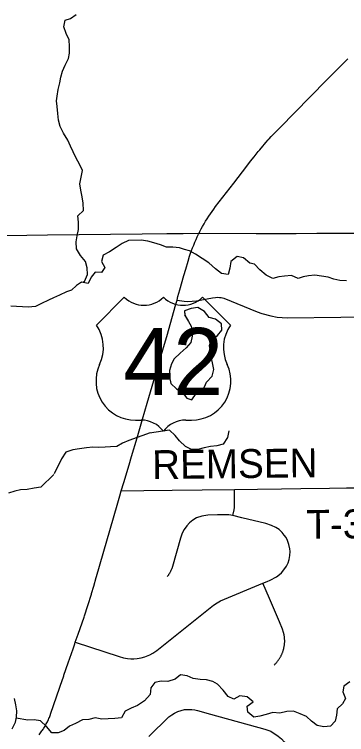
# Model space of a CAD drawing. Extents: x 0 to 34, y 0 to 22.
# Drawn here: x 4.89 to 5.217, y 17.083 to 17.791 of the extents above; entities that cross this region are included whole.
import ezdxf

# ---------------------------------------------------------------- set-up
doc = ezdxf.new("R2010")
doc.units = 0
for name, color, linetype in [('GM_X_County_Road', 7, 'Continuous'), ('GM_X_Major_River', 7, 'Continuous'), ('GM_X_Minor_Lake', 7, 'Continuous'), ('GM_X_Minor_River', 7, 'Continuous'), ('GM_X_Township_Road', 7, 'Continuous'), ('GM_X_Township_Road_Text', 7, 'Continuous'), ('GM_X_US_Location', 7, 'Continuous'), ('GM_X_US_Route', 7, 'Continuous'), ('GM_X_US_Shield', 7, 'Continuous')]:
    doc.layers.add(name, color=color, linetype=linetype)

msp = doc.modelspace()

# ---------------------------------------------------------------- linework, layer by layer
at = {"layer": 'GM_X_County_Road'}
msp.add_lwpolyline([(4.86958, 17.57352), (4.90274, 17.57389), (4.92294, 17.57412), (5.01604, 17.57515), (5.04025, 17.57542), (5.04952, 17.5755), (5.05644, 17.57557), (5.07194, 17.5758), (5.12823, 17.57567), (5.16738, 17.57558), (5.18772, 17.57575), (5.20217, 17.57592), (5.20847, 17.576), (5.22729, 17.57592)], dxfattribs=at)
at = {"layer": 'GM_X_Major_River'}
msp.add_lwpolyline([(4.88817, 17.08829), (4.89138, 17.09493), (4.89251, 17.09987), (4.89269, 17.10594), (4.89174, 17.11201), (4.89041, 17.11827)], dxfattribs=at)
at = {"layer": 'GM_X_Minor_Lake'}
for points in [[(5.07839, 17.42697), (5.07915, 17.42925), (5.08482, 17.43513), (5.08652, 17.44177), (5.08557, 17.44652), (5.08406, 17.45296), (5.0833, 17.45922), (5.08216, 17.46529), (5.08405, 17.47098), (5.0901, 17.47516), (5.09426, 17.48028), (5.09388, 17.48654), (5.0882, 17.49109), (5.08196, 17.49299), (5.07742, 17.49886), (5.07079, 17.50284), (5.06417, 17.50189), (5.05774, 17.49942), (5.05791, 17.49516)], [(5.07839, 17.42697), (5.07915, 17.42925), (5.08482, 17.43513), (5.08652, 17.44177), (5.08557, 17.44652), (5.08406, 17.45296), (5.0833, 17.45922), (5.08216, 17.46529), (5.08405, 17.47098), (5.0901, 17.47516), (5.09426, 17.48028), (5.09388, 17.48654), (5.0882, 17.49109), (5.08196, 17.49299), (5.07742, 17.49886), (5.07079, 17.50284), (5.06417, 17.50189), (5.05774, 17.49942), (5.05793, 17.49468)], [(5.05774, 17.49544), (5.06172, 17.48899), (5.06418, 17.48425), (5.06532, 17.47951), (5.06513, 17.47439), (5.064, 17.46832), (5.05927, 17.463), (5.05341, 17.45769), (5.04736, 17.45219), (5.04472, 17.44744), (5.04302, 17.4408), (5.04283, 17.43435), (5.04416, 17.42791), (5.04983, 17.4226), (5.05551, 17.41938), (5.05986, 17.41369), (5.06478, 17.41179), (5.06913, 17.41805), (5.07537, 17.42071), (5.07839, 17.42697)], [(5.05791, 17.49516), (5.06172, 17.48899), (5.06418, 17.48425), (5.06532, 17.47951), (5.06513, 17.47439), (5.064, 17.46832), (5.05927, 17.463), (5.05341, 17.45769), (5.04736, 17.45219), (5.04472, 17.44744), (5.04302, 17.4408), (5.04283, 17.43435), (5.04416, 17.42791), (5.04983, 17.4226), (5.05551, 17.41938), (5.05986, 17.41369), (5.06478, 17.41179), (5.06913, 17.41805), (5.07537, 17.42071), (5.07839, 17.42697)]]:
    msp.add_lwpolyline(points, dxfattribs=at)
at = {"layer": 'GM_X_Minor_River'}
for points in [[(4.95649, 17.52763), (4.9595, 17.52846), (4.96218, 17.53535), (4.96203, 17.5418), (4.96019, 17.54783), (4.95532, 17.55378), (4.95139, 17.56033), (4.95104, 17.56734), (4.95204, 17.57325), (4.9534, 17.57954), (4.95343, 17.58656), (4.95272, 17.5928), (4.95846, 17.59825), (4.95792, 17.60526), (4.95702, 17.6115), (4.95573, 17.6181), (4.95464, 17.62453), (4.95619, 17.63083), (4.95736, 17.63749), (4.95438, 17.64387), (4.95122, 17.64949), (4.94824, 17.65587), (4.94546, 17.6615), (4.94287, 17.66732), (4.93874, 17.67425), (4.93557, 17.68062), (4.93391, 17.68684), (4.933, 17.69346), (4.93265, 17.70028), (4.93196, 17.70596), (4.93242, 17.71071), (4.9334, 17.71719), (4.93495, 17.72386), (4.93596, 17.7292), (4.93771, 17.73531), (4.94041, 17.74125), (4.94366, 17.74778), (4.94449, 17.75292), (4.94472, 17.75938), (4.94419, 17.766), (4.94139, 17.77239), (4.93898, 17.77878), (4.94034, 17.78546), (4.9456, 17.78691), (4.95118, 17.79102)], [(5.17968, 17.53394), (5.17422, 17.53286), (5.16934, 17.53123), (5.16285, 17.53412), (5.15605, 17.53339), (5.15039, 17.53288), (5.14438, 17.53141), (5.13787, 17.53468), (5.1317, 17.53985), (5.12647, 17.54541), (5.12172, 17.54625), (5.11574, 17.55143), (5.10946, 17.55299), (5.10334, 17.54792), (5.10235, 17.54144), (5.10061, 17.53514), (5.09415, 17.53632), (5.08799, 17.54092), (5.08143, 17.54665), (5.0749, 17.55086), (5.06856, 17.55527), (5.06263, 17.55835), (5.05768, 17.55976), (5.05273, 17.56135), (5.04609, 17.56215), (5.04004, 17.56201), (5.03394, 17.56433), (5.02746, 17.56627), (5.02175, 17.56784), (5.01492, 17.56882), (5.00264, 17.56854), (4.99646, 17.56574), (4.9905, 17.56162), (4.98379, 17.55748), (4.97763, 17.55411), (4.97607, 17.548), (4.97923, 17.5422), (4.97594, 17.537), (4.96988, 17.53762), (4.96583, 17.53259), (4.96295, 17.52627), (4.95649, 17.52763), (4.95165, 17.52448), (4.94646, 17.51981), (4.94159, 17.51799), (4.93485, 17.51499), (4.92886, 17.51239), (4.92381, 17.50999), (4.91707, 17.5068), (4.91109, 17.50363), (4.90411, 17.50309), (4.89843, 17.50334), (4.89237, 17.50357), (4.88688, 17.50402)], [(5.21705, 17.52892), (5.21043, 17.52915), (5.20453, 17.53053), (5.19881, 17.53248), (5.19217, 17.53347), (5.18572, 17.53446), (5.17968, 17.53394)], [(5.02376, 17.37933), (5.00301, 17.37202), (4.99664, 17.36921), (4.99105, 17.36605), (4.985, 17.36572), (4.97953, 17.36521), (4.97291, 17.36506), (4.96761, 17.36532), (4.9612, 17.3646), (4.95441, 17.36368), (4.94782, 17.36258), (4.94106, 17.36053), (4.93668, 17.35379), (4.9294, 17.33905)], [(5.10113, 17.3813), (5.09977, 17.37482), (5.09557, 17.36828), (5.08955, 17.36662), (5.08333, 17.36591), (5.07693, 17.36462), (5.07073, 17.36315), (5.06448, 17.36319), (5.05875, 17.36591), (5.05276, 17.37146), (5.04848, 17.37667), (5.04286, 17.38223), (5.02331, 17.37922)], [(4.92917, 17.33848), (4.91652, 17.326), (4.90992, 17.32509), (4.90314, 17.3238), (4.89653, 17.32326), (4.89089, 17.322), (4.8845, 17.32014)], [(5.1318, 17.10067), (5.12596, 17.09978), (5.11999, 17.10457), (5.11928, 17.11063), (5.12505, 17.11494), (5.11926, 17.11993), (5.11205, 17.12071), (5.10608, 17.11734), (5.10053, 17.12025), (5.09566, 17.1264), (5.09023, 17.13215), (5.08545, 17.1347), (5.07935, 17.13665), (5.07292, 17.13688), (5.06628, 17.13767), (5.06017, 17.14038), (5.05371, 17.14155), (5.04832, 17.13726), (5.04138, 17.13501), (5.03457, 17.13523), (5.02836, 17.13376), (5.02451, 17.12855), (5.0239, 17.12208), (5.01837, 17.11589), (5.01148, 17.11136), (5.0053, 17.10875), (4.99932, 17.10558), (4.99569, 17.09924), (4.98927, 17.09852), (4.98248, 17.09798), (4.97643, 17.09784), (4.96978, 17.09921), (4.96358, 17.09754), (4.95754, 17.09703), (4.95062, 17.09345), (4.94463, 17.09104), (4.93924, 17.08674), (4.93343, 17.08452), (4.92738, 17.08438), (4.92194, 17.0907), (4.91615, 17.09607), (4.90988, 17.09725), (4.90365, 17.09673), (4.89221, 17.09883)], [(5.22009, 17.1344), (5.21414, 17.13028), (5.21332, 17.12457), (5.21593, 17.11799), (5.21302, 17.11299), (5.20765, 17.10812), (5.20705, 17.10165), (5.20585, 17.09594), (5.20105, 17.09089), (5.19445, 17.09017), (5.18818, 17.09154), (5.1826, 17.09578), (5.17757, 17.10059), (5.17146, 17.10292), (5.16478, 17.10561), (5.15817, 17.10527), (5.15121, 17.10359), (5.14458, 17.10438), (5.138, 17.10252), (5.1318, 17.10067)]]:
    msp.add_lwpolyline(points, dxfattribs=at)
at = {"layer": 'GM_X_Township_Road'}
for points in [[(5.05041, 17.51006), (5.05727, 17.50895), (5.06029, 17.50864), (5.0653, 17.50882), (5.06936, 17.50944), (5.0853, 17.51236), (5.08813, 17.5127), (5.08982, 17.51285), (5.09195, 17.51272), (5.09358, 17.51248), (5.09638, 17.51184), (5.12913, 17.49854), (5.13367, 17.49673), (5.14237, 17.49444), (5.14865, 17.49329), (5.15872, 17.49252), (5.21139, 17.49312), (5.24624, 17.49378)], [(4.99555, 17.3225), (5.01777, 17.3227), (5.04547, 17.32305), (5.07495, 17.32329), (5.10669, 17.32359), (5.12947, 17.32399), (5.15286, 17.32423), (5.17216, 17.32456), (5.20008, 17.32503), (5.21676, 17.32534), (5.26254, 17.32544)], [(5.10509, 17.29829), (5.10611, 17.30235), (5.10622, 17.30283), (5.10632, 17.30332), (5.10641, 17.3038), (5.1065, 17.30429), (5.10658, 17.30478), (5.10665, 17.30527), (5.10671, 17.30576), (5.10675, 17.30626), (5.1068, 17.30675), (5.10683, 17.30725), (5.10669, 17.32359)], [(4.95031, 17.17343), (4.99347, 17.15943), (4.99778, 17.15822), (5.00159, 17.15746), (5.00491, 17.15715), (5.00799, 17.15721), (5.01125, 17.15742), (5.01513, 17.15813), (5.01873, 17.15921), (5.02344, 17.16108), (5.02667, 17.16278), (5.03051, 17.16551), (5.06142, 17.19029), (5.08628, 17.21), (5.08965, 17.2123), (5.09297, 17.2141), (5.13476, 17.23159), (5.13886, 17.23327), (5.142, 17.23466), (5.14812, 17.23765), (5.15104, 17.23999), (5.15301, 17.2419), (5.15534, 17.24461), (5.15789, 17.24834), (5.15953, 17.2517), (5.16051, 17.25495), (5.16121, 17.25864), (5.16142, 17.26258), (5.16113, 17.26541), (5.16031, 17.26972), (5.159, 17.27353), (5.15756, 17.27636), (5.15575, 17.2789), (5.15366, 17.28149), (5.15067, 17.28424), (5.14751, 17.28637), (5.14328, 17.28838), (5.13771, 17.29018), (5.11396, 17.29589), (5.10509, 17.29829), (5.10115, 17.29874), (5.08995, 17.29866), (5.08051, 17.29842), (5.07473, 17.29764), (5.06948, 17.29579), (5.06578, 17.29366), (5.06254, 17.29087), (5.05984, 17.288), (5.05733, 17.28435), (5.05549, 17.28082), (5.05372, 17.27573), (5.04585, 17.24804), (5.04556, 17.2471), (5.0454, 17.24663), (5.04523, 17.24616), (5.04505, 17.2457), (5.04487, 17.24524), (5.04468, 17.24478), (5.04448, 17.24433), (5.04427, 17.24388), (5.04405, 17.24343), (5.04383, 17.24298), (5.0436, 17.24255), (5.04336, 17.24211), (5.04311, 17.24168), (5.04286, 17.24125), (5.0426, 17.24083), (5.04233, 17.24041), (5.04205, 17.24), (5.04177, 17.23959), (5.04148, 17.23919), (5.04119, 17.23879), (5.04057, 17.23801)], [(5.14565, 17.15089), (5.14648, 17.15169), (5.14689, 17.15211), (5.14728, 17.15252), (5.14767, 17.15295), (5.14806, 17.15339), (5.14843, 17.15382), (5.1488, 17.15427), (5.14916, 17.15472), (5.14951, 17.15518), (5.14985, 17.15565), (5.15019, 17.15612), (5.15051, 17.15659), (5.15083, 17.15708), (5.15115, 17.15757), (5.15145, 17.15806), (5.15174, 17.15856), (5.15202, 17.15906), (5.1523, 17.15957), (5.15257, 17.16008), (5.15282, 17.1606), (5.15307, 17.16112), (5.15331, 17.16165), (5.15354, 17.16218), (5.15376, 17.16272), (5.15398, 17.16326), (5.15418, 17.1638), (5.15437, 17.16434), (5.15455, 17.16489), (5.15473, 17.16545), (5.15489, 17.166), (5.15504, 17.16656), (5.15519, 17.16712), (5.15532, 17.16768), (5.15545, 17.16825), (5.15556, 17.16881), (5.15567, 17.16938), (5.15576, 17.16995), (5.15585, 17.17053), (5.15592, 17.1711), (5.15599, 17.17168), (5.15604, 17.17225), (5.15609, 17.17283), (5.15612, 17.17341), (5.15594, 17.17854), (5.15557, 17.18085), (5.15504, 17.1832), (5.15398, 17.18623), (5.15092, 17.19354), (5.14121, 17.21635), (5.13476, 17.23159)], [(5.02251, 17.08065), (5.04235, 17.09995), (5.04504, 17.10207), (5.04795, 17.10376), (5.05098, 17.10543), (5.05425, 17.10644), (5.05778, 17.10725), (5.06089, 17.10748), (5.06488, 17.10738), (5.06792, 17.10695), (5.07034, 17.1063), (5.08334, 17.10267), (5.13654, 17.08812), (5.14255, 17.08585), (5.14973, 17.08125), (5.15284, 17.07859), (5.15552, 17.07557), (5.15818, 17.07188), (5.16053, 17.0676), (5.16275, 17.06153), (5.16372, 17.05697), (5.1642, 17.05363), (5.16476, 17.02423)]]:
    msp.add_lwpolyline(points, dxfattribs=at)
at = {"layer": 'GM_X_US_Route'}
for points in [[(4.93545, 17.13036), (4.93888, 17.14043), (4.93912, 17.14112), (4.94329, 17.15316), (4.94813, 17.16715), (4.94983, 17.17207), (4.95031, 17.17343), (4.95308, 17.18145), (4.95891, 17.19828), (4.95929, 17.19945), (4.9626, 17.20952), (4.9661, 17.22083), (4.96626, 17.22141), (4.9684, 17.22878), (4.97085, 17.23727), (4.97114, 17.23827), (4.99141, 17.30833), (4.99404, 17.31743), (4.99555, 17.3225), (4.99803, 17.33057), (5.00316, 17.34798), (5.00561, 17.35631), (5.011, 17.37459), (5.01635, 17.39278), (5.02106, 17.40875), (5.03811, 17.46663), (5.04023, 17.47417), (5.0492, 17.50611), (5.05041, 17.51006), (5.05126, 17.51345), (5.05217, 17.5167), (5.05313, 17.52011), (5.05712, 17.53415), (5.05888, 17.54032), (5.06117, 17.54833), (5.06271, 17.5533), (5.06363, 17.55605), (5.06461, 17.55878), (5.06563, 17.56149), (5.0667, 17.56419), (5.06782, 17.56687), (5.06898, 17.56953), (5.07019, 17.57216), (5.07144, 17.57478), (5.07194, 17.5758), (5.07274, 17.57737), (5.07409, 17.57995), (5.07548, 17.58249), (5.07691, 17.58501), (5.07839, 17.58751), (5.07991, 17.58998), (5.08147, 17.59243), (5.08308, 17.59484), (5.08473, 17.59723), (5.08642, 17.59959), (5.08815, 17.60191), (5.10613, 17.62516), (5.11896, 17.64175), (5.12263, 17.6465), (5.126, 17.65085), (5.13013, 17.65605), (5.13156, 17.65785), (5.13461, 17.6615), (5.13623, 17.66337), (5.13773, 17.66511), (5.13987, 17.66749), (5.14091, 17.66865), (5.14291, 17.6708), (5.14416, 17.67214), (5.14746, 17.67558), (5.14966, 17.67781), (5.1506, 17.67877), (5.15165, 17.67984), (5.18085, 17.70958), (5.18438, 17.71314), (5.18443, 17.71319), (5.19439, 17.72323), (5.21666, 17.74567), (5.2182, 17.74722)], [(4.91469, 17.08247), (4.91542, 17.08337), (4.91613, 17.08429), (4.91682, 17.08522), (4.9175, 17.08617), (4.91817, 17.08713), (4.91882, 17.08809), (4.91905, 17.08845), (4.91945, 17.08907), (4.92006, 17.09006), (4.92065, 17.09106), (4.92123, 17.09207), (4.92179, 17.09309), (4.92233, 17.09412), (4.92286, 17.09516), (4.92336, 17.09621), (4.92385, 17.09727), (4.92432, 17.09833), (4.92477, 17.0994), (4.92485, 17.0996), (4.9252, 17.10048), (4.92561, 17.10157), (4.92633, 17.10362), (4.9348, 17.12845), (4.93545, 17.13036)]]:
    msp.add_lwpolyline(points, dxfattribs=at)
at = {"layer": 'GM_X_US_Shield'}
for p, q in [((4.9985, 17.51281), (4.97103, 17.48534)), ((5.10287, 17.48534), (5.0754, 17.51281)), ((5.00948, 17.39196), (5.01498, 17.39196)), ((5.05892, 17.39196), (5.06442, 17.39196))]:
    msp.add_line(p, q, dxfattribs=at)
for centre, radius, start, end in [((5.01772, 17.53243), 0.02747, 225.573, 314.427), ((5.05618, 17.53243), 0.02747, 225.573, 314.427), ((4.93953, 17.46329), 0.03845, 334.54712, 35.00093), ((5.13437, 17.46329), 0.03845, 144.99907, 205.45288), ((5.00906, 17.43041), 0.03845, 154.83192, 270.63826), ((5.06484, 17.43041), 0.03845, 269.36174, 25.16808), ((5.01498, 17.36449), 0.02747, 36.8699, 90), ((5.05892, 17.36449), 0.02747, 90, 143.1301)]:
    msp.add_arc(centre, radius, start, end, dxfattribs=at)

# ---------------------------------------------------------------- texts
at = {"layer": 'GM_X_Township_Road_Text'}
for s, rotation, p in [('REMSEN', 0.6783, (5.02599, 17.33389)), ('T-37', 0.70694, (5.17756, 17.27507))]:
    msp.add_text(s, height=0.028409, rotation=rotation, dxfattribs=at).set_placement(p)
at = {"layer": 'GM_X_US_Location'}
for s, p in [('0', (5.03691, 17.44912)), ('/', (5.03692, 17.44912))]:
    msp.add_text(s, height=0.0000947, dxfattribs=at).set_placement(p)
msp.add_text('42', height=0.0000947, rotation=0.00001, dxfattribs=at).set_placement((5.01737, 17.42952))
at = {"layer": 'GM_X_US_Shield'}
msp.add_text('42', height=0.065918, dxfattribs=at).set_placement((4.99756, 17.41668))

doc.saveas('drawing.dxf')
